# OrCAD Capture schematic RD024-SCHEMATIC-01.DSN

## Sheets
1 3: size A3
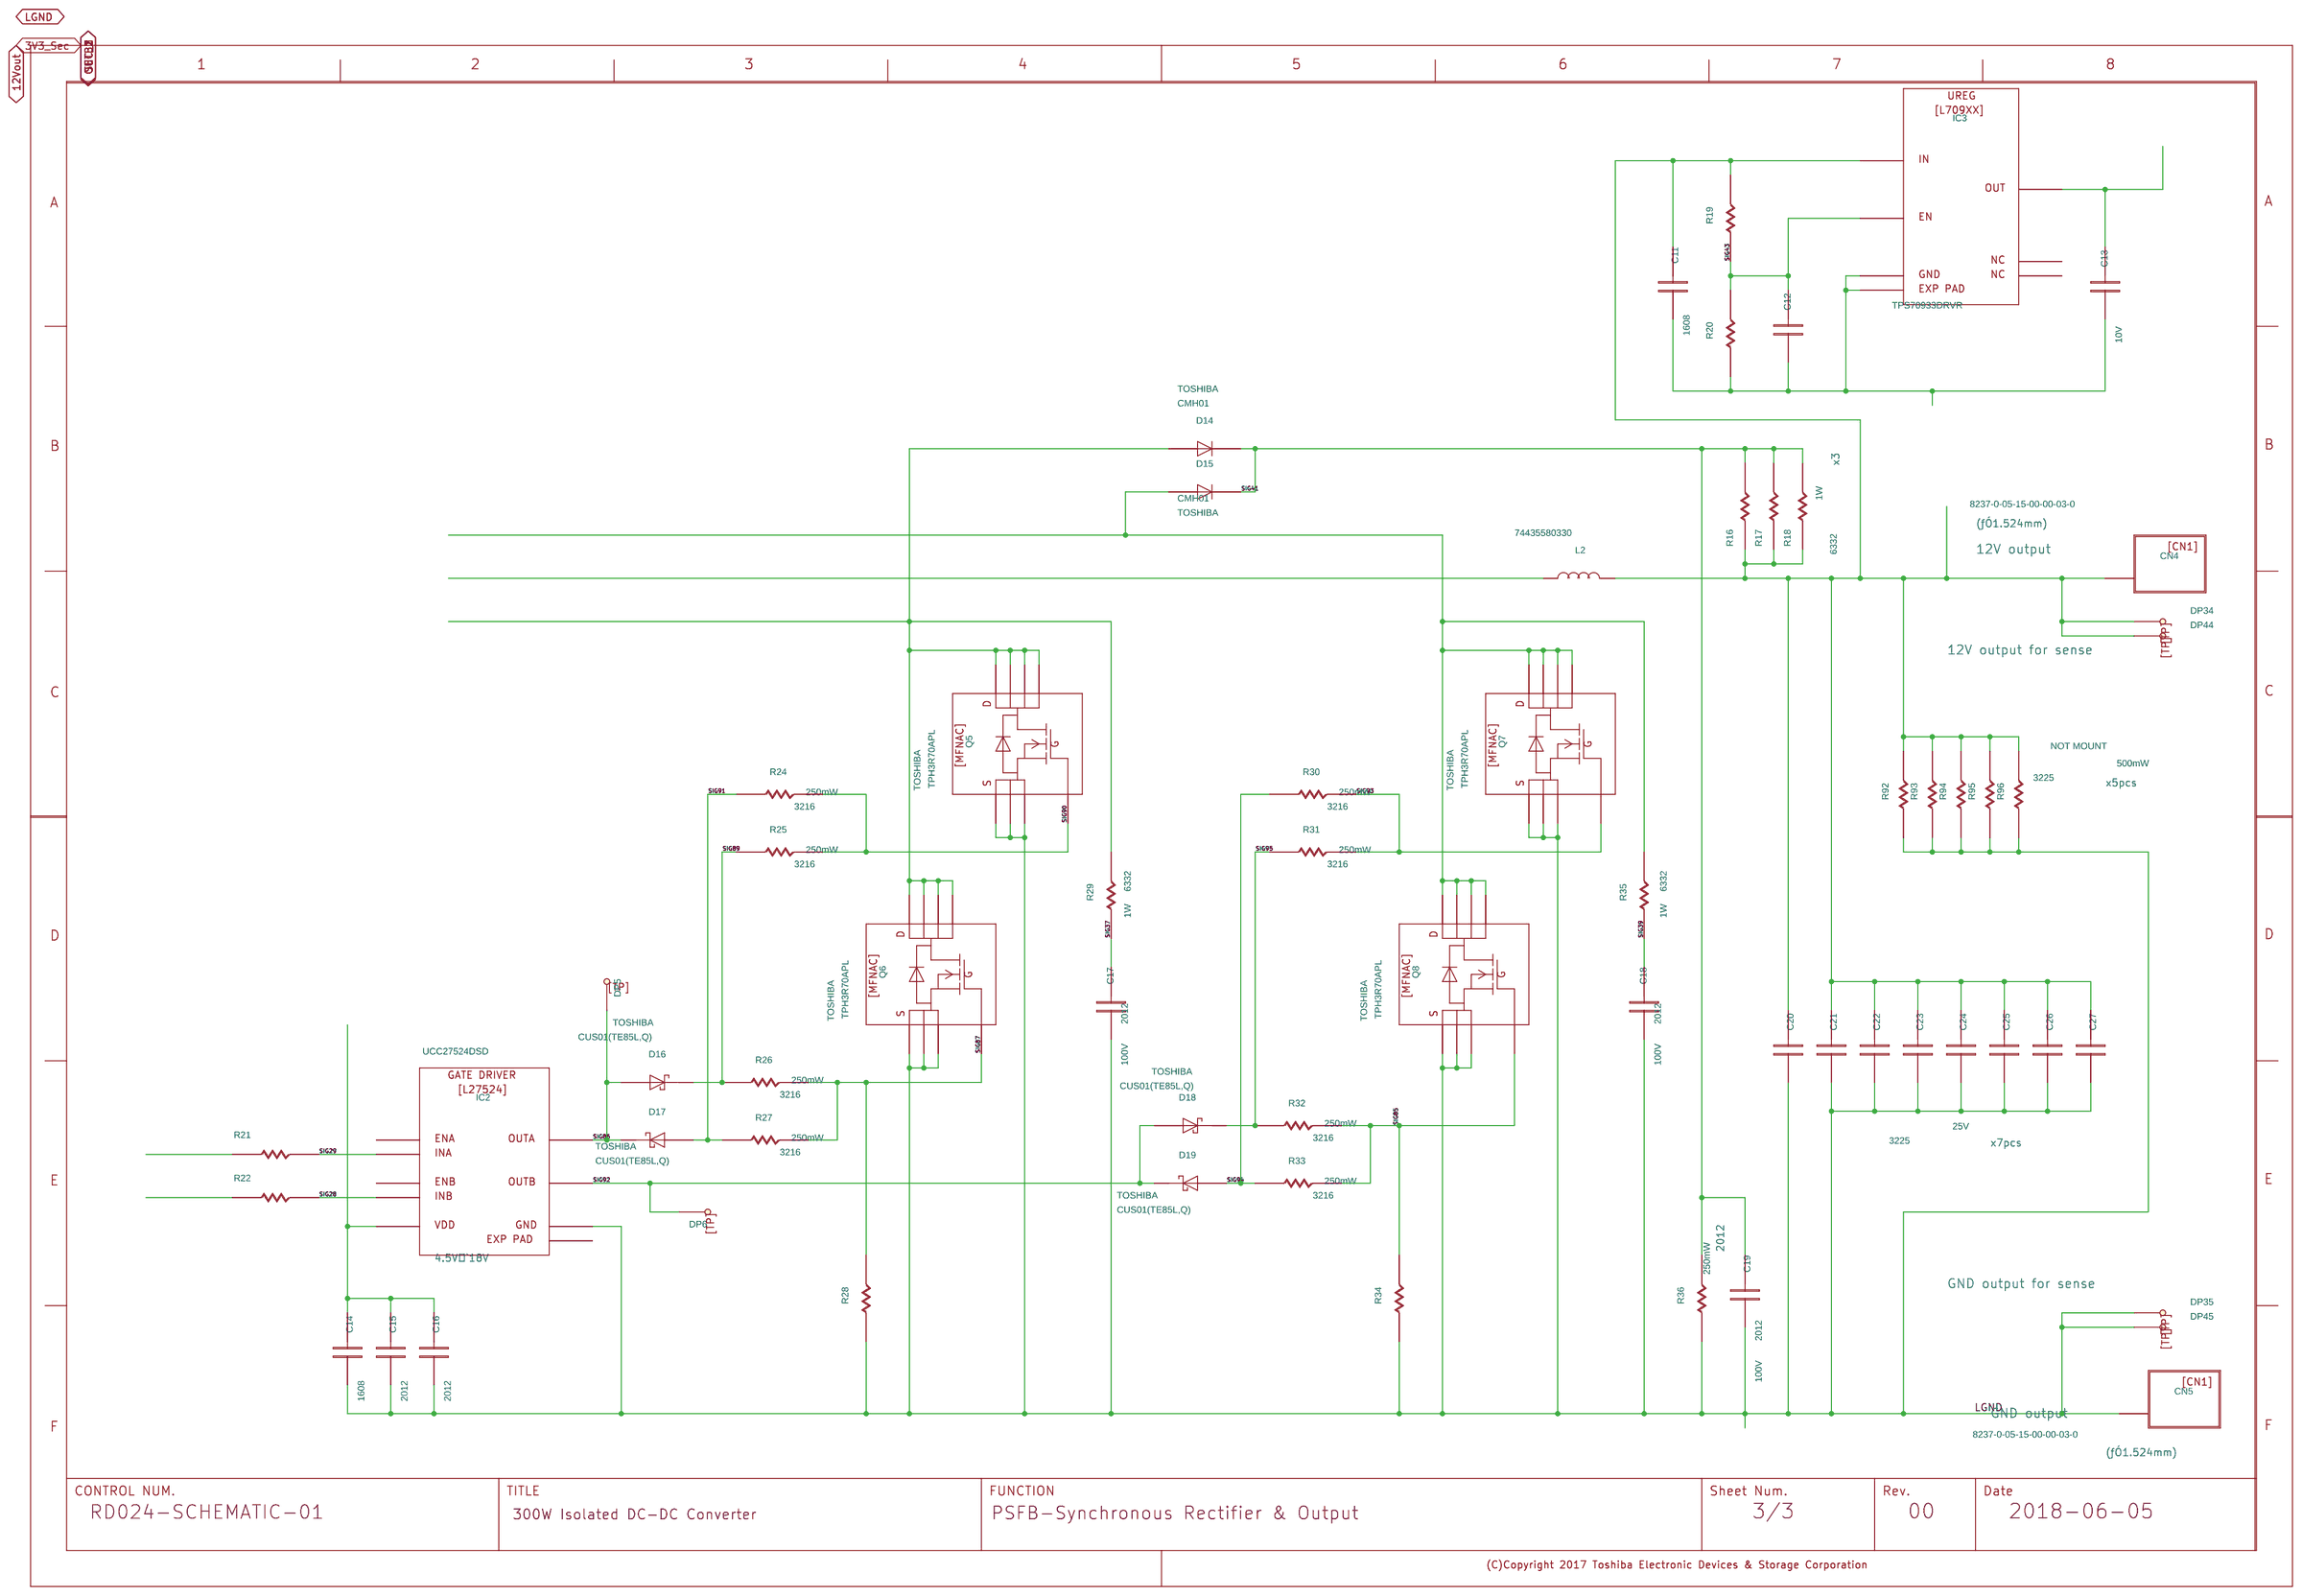
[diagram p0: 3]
2 2: size A3
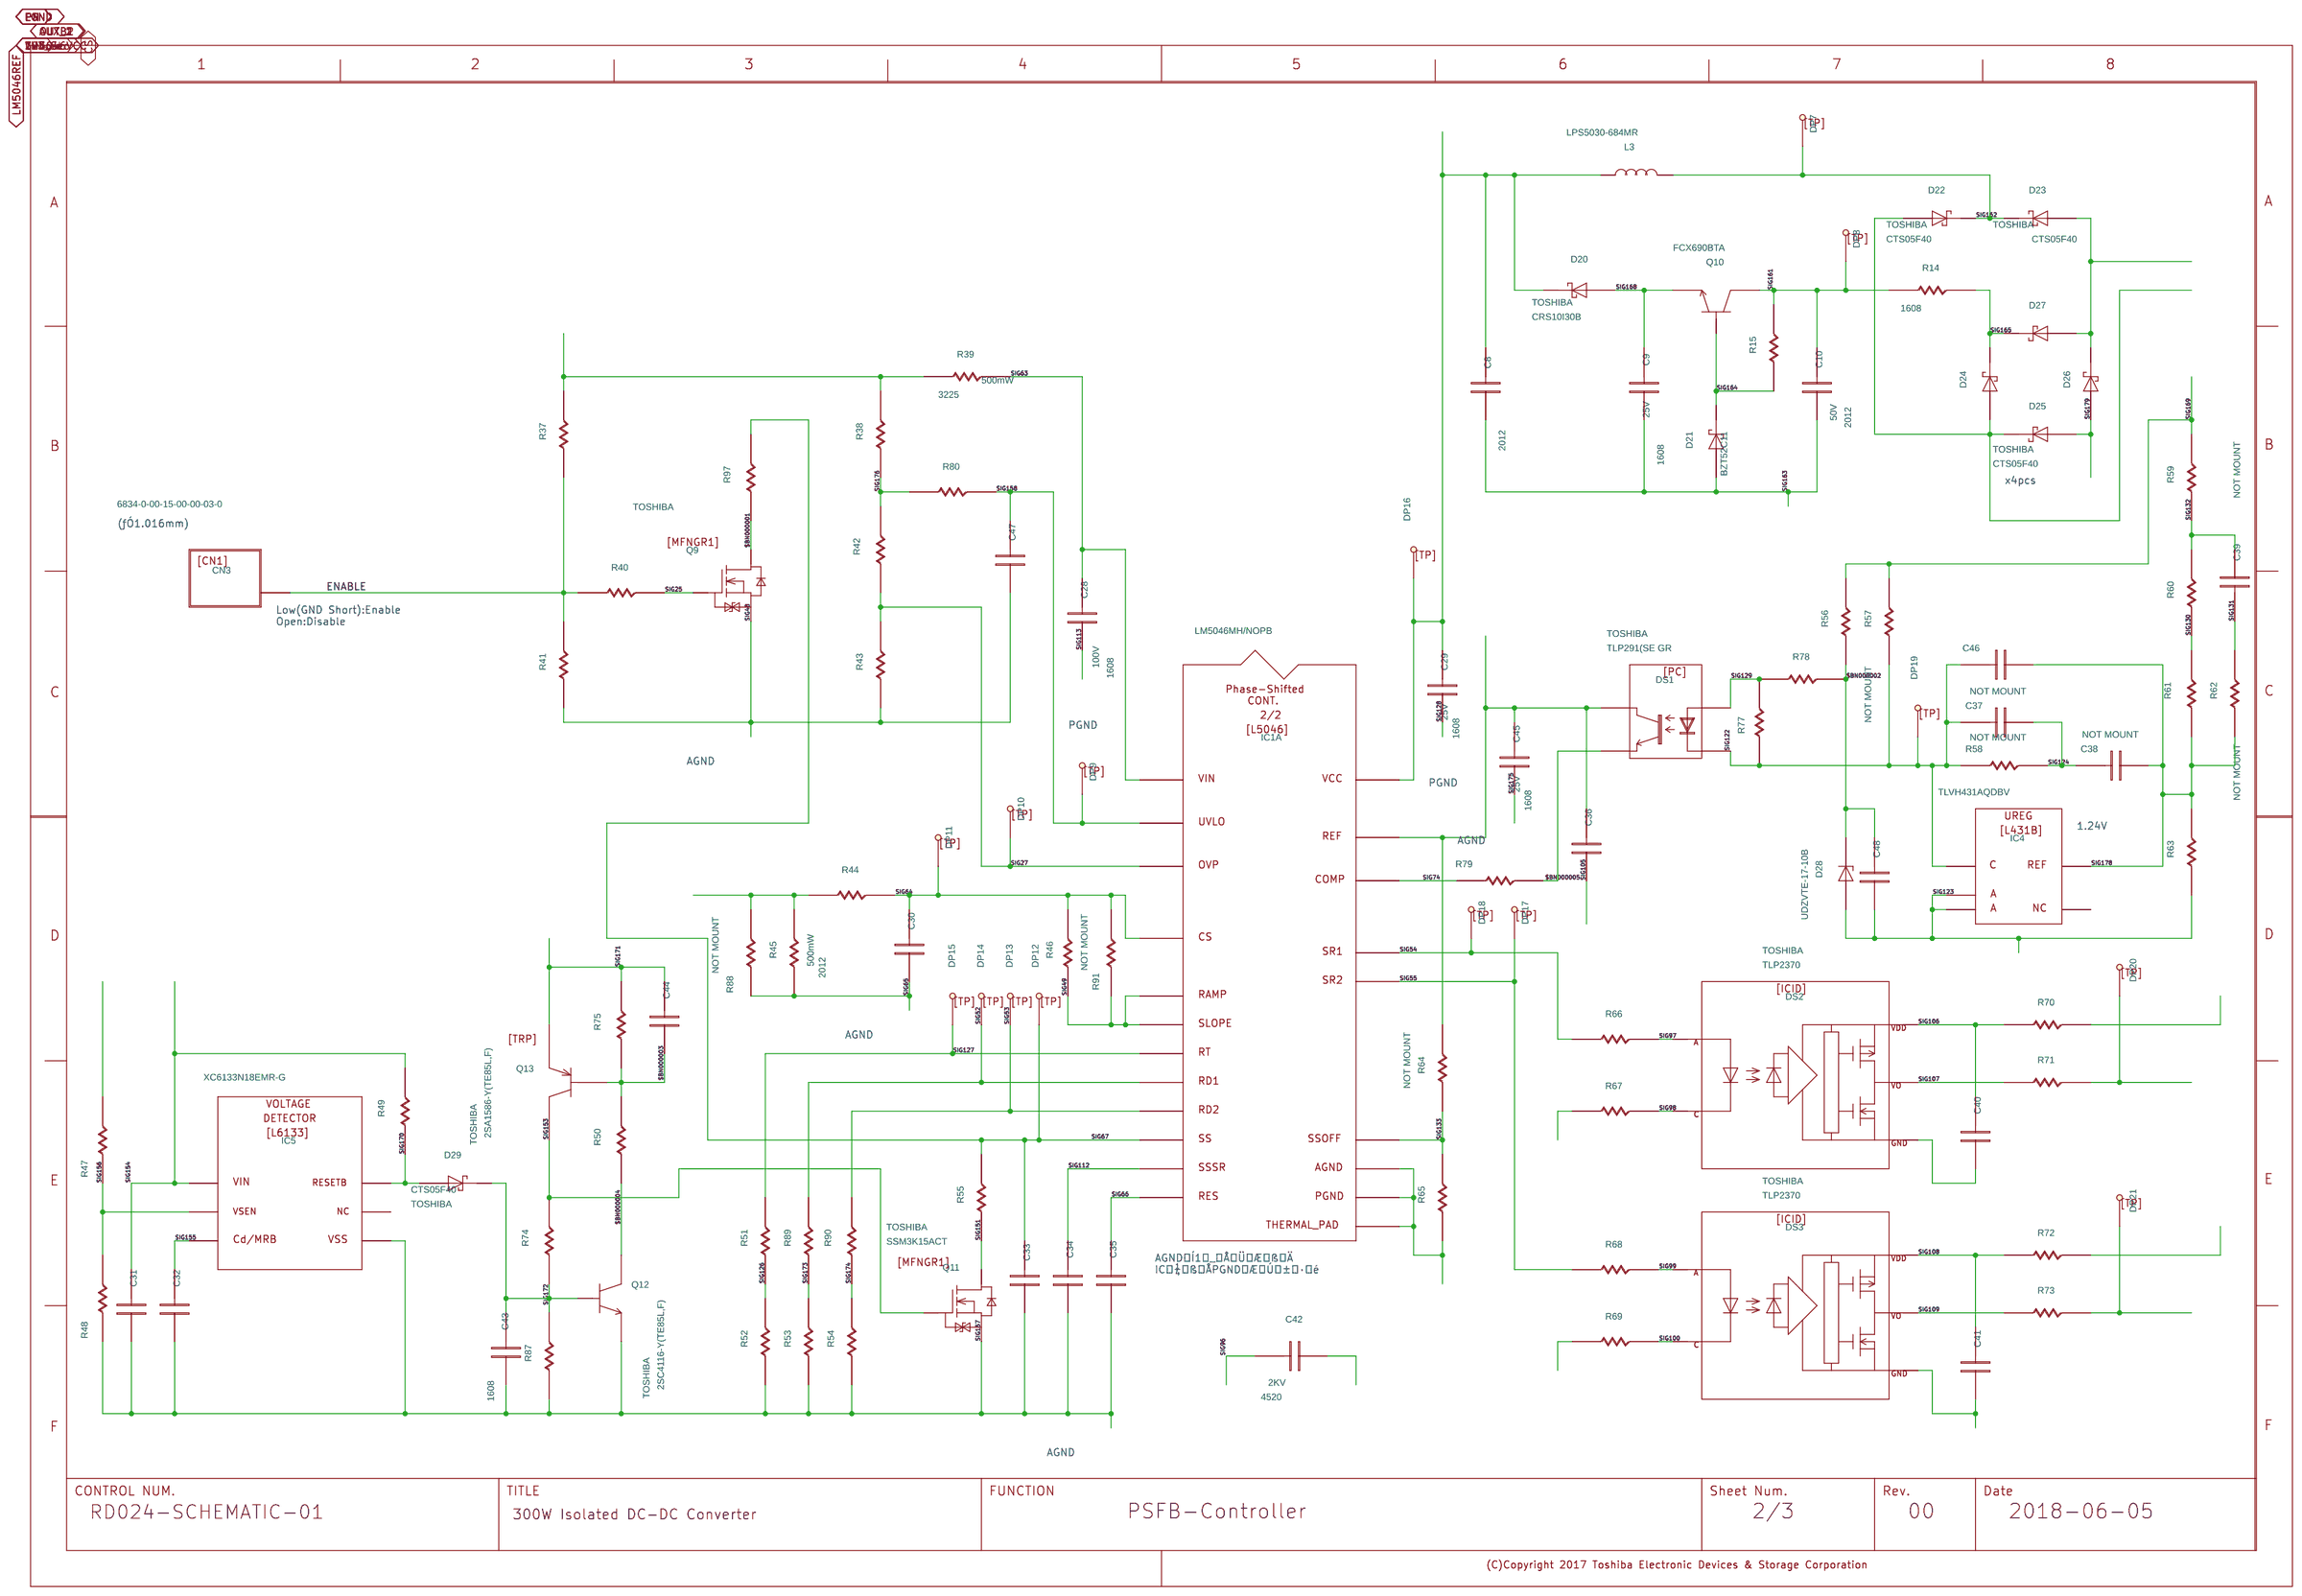
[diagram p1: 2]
3 1: size A3
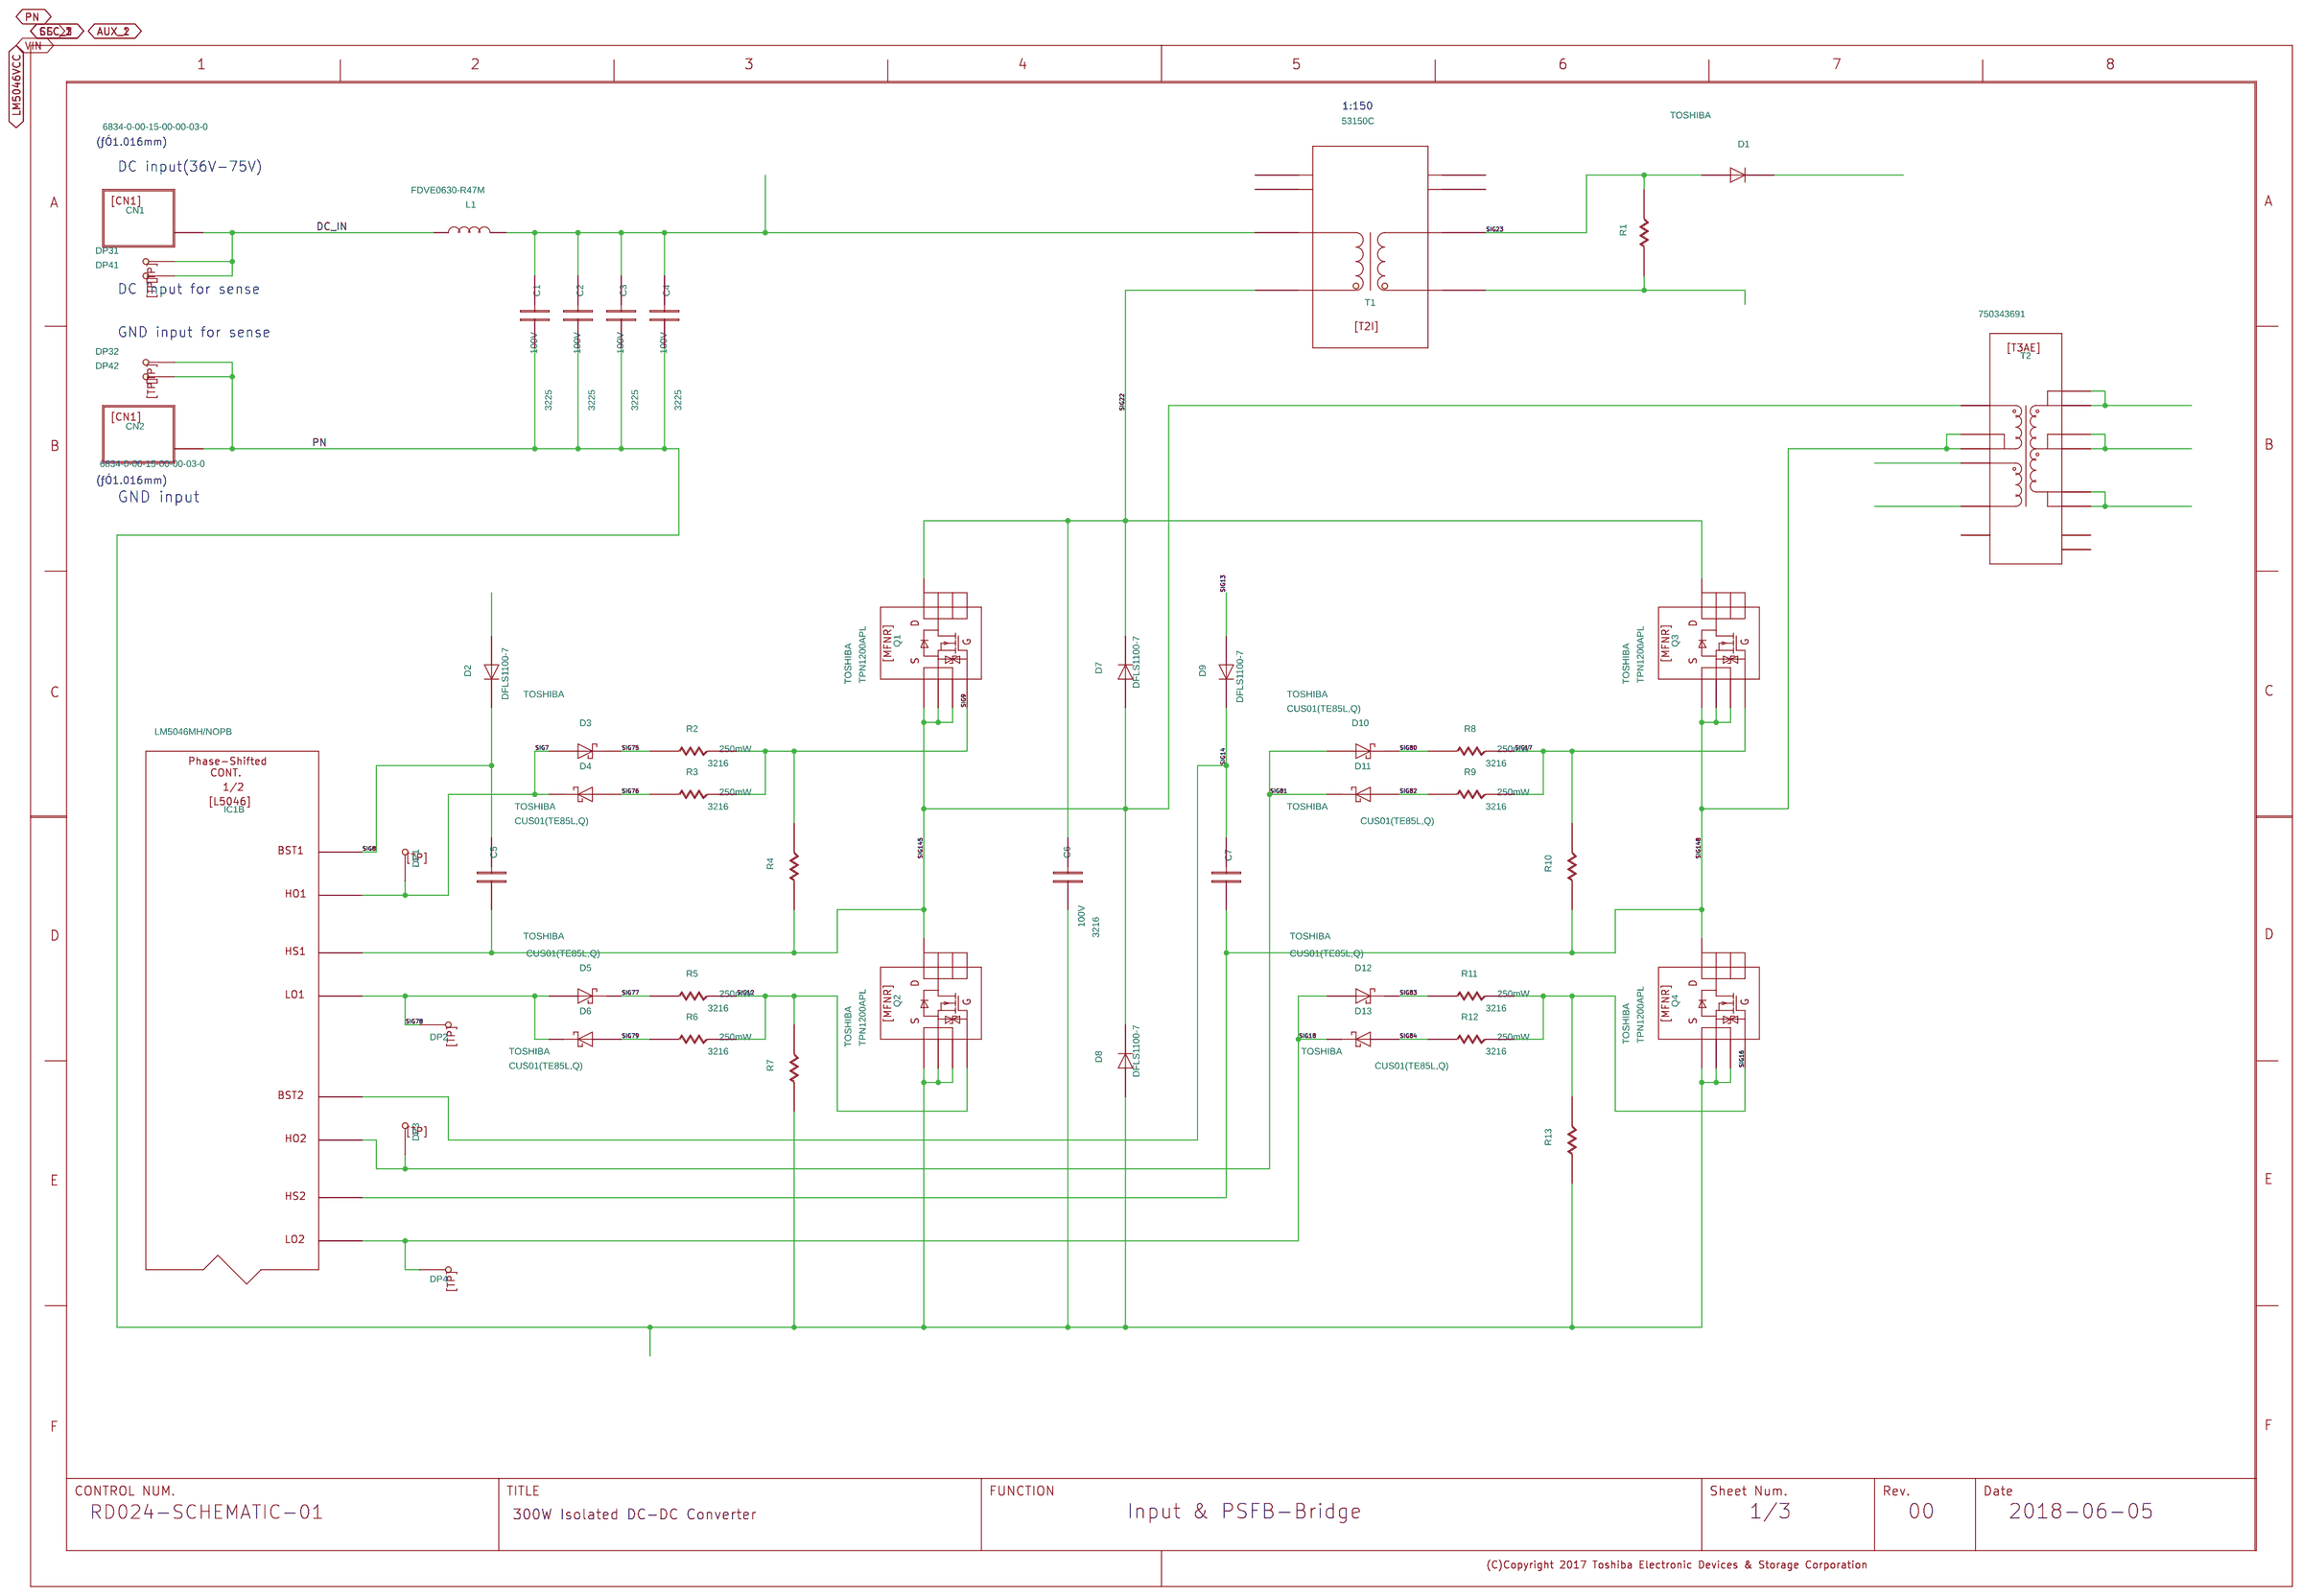
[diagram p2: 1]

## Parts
sheet 1
C1  10uF
C2  10uF
C3  10uF
C4  10uF
C5  100nF
C6  470nF
C7  100nF
CN1  CN1
CN2  CN1
D1  1SS352(TPH3,F)1-1E1A
D2  D
D3  CUS01(TE85L,Q)
D4  CUS01(TE85L,Q)
D5  CUS01(TE85L,Q)
D6  CUS01(TE85L,Q)
D7  D
D8  D
D9  D
D10  CUS01(TE85L,Q)
D11  CUS01(TE85L,Q)
D12  CUS01(TE85L,Q)
D13  CUS01(TE85L,Q)
DP1  TP
DP2  TP
DP3  TP
DP4  TP
DP31  TP
DP32  TP
DP41  TP
DP42  TP
L1  0.47uH
Q1  MFNR
Q2  MFNR
Q3  MFNR
Q4  MFNR
R1  10K(J)
R2  10(G)
R3  0
R4  10K(J)
R5  10(G)
R6  0
R7  10K(J)
R8  0
R9  0
R10  10K(J)
R11  0
R12  0
R13  10K(J)
T1  T2I
T2  T3AE
U?#2  WAKU_DEF100
sheet 2
C8  2.2uF
C9  1uF
C10  1uF
C28  100nF
C29  1uF
C30  100pF
C31  100nF
C32  100nF
C33  22nF
C34  100nF
C35  10nF
C36  100nF
C37  100pF
C38  15nF
C39  15nF
C40  100nF
C41  100nF
C42  1500pF
C43  1uF
C44  100nF
C45  1uF
C46  100nF
C47  1nF
C48  100nF
CN3  CN1
D20  SBD
D21  SBD
D22  SBD
D23  SBD
D24  SBD
D25  SBD
D26  SBD
D27  SBD
D28  ZD
D29  SBD
DP7  TP
DP8  TP
DP9  TP
DP10  TP
DP11  TP
DP12  TP
DP13  TP
DP14  TP
DP15  TP
DP16  TP
DP17  TP
DP18  TP
DP19  TP
DP20  TP
DP21  TP
DS1  PC
DS2  ICID
DS3  ICID
IC1  L5046_1  (sections A,B)
IC4  L431B
IC5  L6133
L3  680uH
Q9  SSM3K15ACT
Q10  TRN
Q11  SSM3K15ACT
Q12  2SC4116-Y(TE85L,F)
Q13  2SA1586-Y(TE85L,F)
R14  2.2(J)
R15  5.1K(J)
R37  1M(J)
R38  100K(J)
R39  20
R40  100K(J)
R41  220K(J)
R42  2.49K(D)
R43  1.6K(D)
R44  1K(J)
R45  8.2(F)
R46  3.3K(D)
R47  110K(D)
R48  16K(D)
R49  10K(J)
R50  10K(J)
R51  27K(D)
R52  0(X)
R53  20K(D)
R54  20K(D)
R55  1K(J)
R56  330(J)
R57  10K(J)
R58  620(F)
R59  49.9(F)
R60  1.2K(D)
R61  18K(D)
R62  182(F)
R63  2.2K(D)
R64  0(X)
R65  0(X)
R66  1K(F)
R67  910(F)
R68  1K(F)
R69  910(F)
R70  0(X)
R71  0(X)
R72  0(X)
R73  0(X)
R74  10K(J)
R75  10K(J)
R77  470(J)
R78  1.2K(F)
R79  2.2K(J)
R80  1(J)
R87  10K(J)
R88  9.1(J)
R89  7.5K(D)
R90  10K(J)
R91  0(X)
R97  1K(J)
U?#1  WAKU_DEF100
sheet 3
C11  1uF
C12  100nF
C13  2.2uF
C14  1uF
C15  10uF
C16  10uF
C17  470pF
C18  470pF
C19  220nF
C20  100nF
C21  22uF
C22  22uF
C23  22uF
C24  22uF
C25  22uF
C26  22uF
C27  22uF
CN4  CN1
CN5  CN1
D14  D
D15  D
D16  CUS01(TE85L,Q)
D17  CUS01(TE85L,Q)
D18  CUS01(TE85L,Q)
D19  CUS01(TE85L,Q)
DP5  TP
DP6  TP
DP34  TP
DP35  TP
DP44  TP
DP45  TP
IC2  L27524
IC3  L709XXA
L2  3.3uH
Q5  MFNAC
Q6  MFNAC
Q7  MFNAC
Q8  MFNAC
R16  6.8K
R17  6.8K
R18  6.8K
R19  240K(F)
R20  24K(F)
R21  1K(J)
R22  1K(J)
R24  0
R25  0
R26  0
R27  0
R28  10K(J)
R29  15(J)
R30  0
R31  0
R32  0
R33  0
R34  10K(J)
R35  15(J)
R36  100K
R92  750(F)
R93  750(F)
R94  750(F)
R95  750(F)
R96  750(F)
U?#3  WAKU_DEF100

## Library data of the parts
C1-C4 = C: ADSCNVFLAG: ON; ADSCOMPONENTNAME: C_3225; ADSMODELNAME: s_GRM32EC80G107ME20L; CAPACITANCETOLE: M; CDMASTERCADCELG: DC903A; COMP: PRT_2; COMPONENTTYPE: 4; GCOUNT: 1; ICX_PART_MODEL: CON_100U; MAXGCOUNT: 1; NOMINALCAPACITA: 100u; OUMECLASSIFICATION: ƒZƒ‰ƒ~ƒbƒNƒRƒ“ƒfƒ“ƒT; OUMEMAKER: MRT ºc»ì; OUMEMAKERKATAMEI: GRM32EC80G107ME20L; QUADMODEL: CON_100U; RATEDVOLTAGE: 4; SIZECODESMD: 3225; SQ_PART_MODEL: CON_100U; VALUE2: 100V; VALUE3: GRM32EC72A106KE05#
C5 C7 C12 C20 C31 C32 C34 C36 C40 C41 C44 C46 C48 = C: ADSCNVFLAG: ON; ADSCOMPONENTNAME: C_1005; ADSMODELNAME: s_GRM155R71E104KE14D; CAPACITANCETOLE: K; CDMASTERCADCELG: KC0005; COMP: PRT_4; COMPONENTTYPE: 4; GCOUNT: 1; ICX_PART_MODEL: CON_100N; MAXGCOUNT: 1; NOMINALCAPACITA: 100n; OUMECLASSIFICATION: ƒZƒ‰ƒ~ƒbƒNƒRƒ“ƒfƒ“ƒT; OUMEMAKER: MRT ºc»ì; OUMEMAKERKATAMEI: GRM155R71E104KE14D; QUADMODEL: CON_100N; RATEDVOLTAGE: 25; SIZECODESMD: 1005; SQ_PART_MODEL: CON_100N; VALUE2: 25V; VALUE3: GRM155R71E104KE14#
C6 = C: COMP: PRT_13; COMPCOMMENT: 3216; COMPONENTTYPE: 4; VALUE2: 100V; VALUE3: GRM31MR72A474KA35#
CN1-CN3 = CN1: COMP: PRT_16; COMPONENTTYPE: 4; VALUE3: 6834-0-00-15-00-00-03-0
D1 = D: COMP: PRT_3; COMPONENTTYPE: 4; GCOUNT: 1; MAXGCOUNT: 1; USERCOMPTEXT3: TOSHIBA
D2 D7-D9 = D: COMP: PRT_9; COMPONENTTYPE: 4; VALUE3: DFLS1100-7
D3-D6 D10-D13 D16-D19 = SBD: COMP: PRT_7; COMPONENTTYPE: 4; GCOUNT: 1; MAXGCOUNT: 1; OUMEPARTTYPE: D; USERCOMPTEXT3: TOSHIBA
DP1-DP21 DP31 DP32 DP34 DP35 DP41 DP42 DP44 DP45 = TP: COMP: PRT_10; COMPONENTTYPE: 4; GCOUNT: 1; MAXGCOUNT: 1
L1 = L: ADSCNVFLAG: ON; ADSCOMPONENTNAME: L_SMD; ADSMODELNAME: s_FDV0630_4R7M_P3; CDMASTERCADCELG: KD0074; COMP: PRT_1; COMPONENTTYPE: 4; GCOUNT: 1; INDUCTANCEMAX: 0; INDUCTANCEMIN: 0; MAXGCOUNT: 1; MOUNTINGFORMSMD: SMD; NOMINALINDUCTA1: 4.7u; NOMINALINDUCTA2: M; OUMECLASSIFICATION: •\–ÊŽÀ‘•—pŒÅ’èƒRƒCƒ‹; OUMEMAKER: TKO “ŒŒõ; OUMEMAKERKATAMEI: FDV0630-4R7M=P3; RATEDCURRENT: 3.3; VALUE3: FDVE0630-R47M
Q1-Q4 = MFNR: COMP: PRT_15; COMPONENTTYPE: 4; USERCOMPTEXT3: TOSHIBA; VALUE3: TPN1200APL
R1 R4 R7 R10 R13 R28 R34 R49 R50 R74 R75 R87 R90 = R: COMP: PRT_8; COMPONENTTYPE: 4; GCOUNT: 1; MAXGCOUNT: 1; SIZECODESMD: 1005; VALUE2: 63mW; VALUE3: ERJ2GEJ103X
R2 R5 = R: COMP: PRT_14; COMPONENTTYPE: 4; GCOUNT: 1; MAXGCOUNT: 1; SIZECODESMD: 3216; VALUE2: 250mW; VALUE3: RK73B2BTTD100G
R3 R6 R8 R9 R11 R12 R24-R27 R30-R33 = R: COMP: PRT_12; COMPCOMMENT: 3216; COMPONENTTYPE: 4; VALUE2: 250mW; VALUE3: RK73Z2BRTTD
T1 = T2I: COMP: PRT_11; COMPONENTTYPE: 4; VALUE3: 53150C
T2 = T3AE: COMP: PRT_17; COMPONENTTYPE: 4; VALUE3: 750343691
U?#2 = WAKU_DEF100: COMPONENTTYPE: 2; DATE: 2018-06-05; DESIGNED: TOSHIBA; DRAWINGNUMBER: RD024-SCHEMATIC-01; FUNCTION: Input & PSFB-Bridge; PAGENUMBER: 01; REVISION: 00; SAVEAREA0: -45080,-4508,463680,304612; SHEETNUMBER: 1/3; TIME: 09:33:31; TITLE: 300W Isolated DC-DC Converter; UPDATEDATE: 2018/06/22; UPDATETIME: 14:09:13; UPDATEUSER: d5009410
C8 = C: ADSCNVFLAG: ON; ADSCOMPONENTNAME: C_2012; ADSMODELNAME: s_GRM21BR71E225KA73L@@; CAPACITANCETOLE: K; COMP: PRT_39; COMPONENTTYPE: 4; GCOUNT: 1; ICX_PART_MODEL: CON_2.2U; MAXGCOUNT: 1; NOMINALCAPACITA: 2.2u; OUMECLASSIFICATION: ƒZƒ‰ƒ~ƒbƒNƒRƒ“ƒfƒ“ƒT; OUMEMAKER: MRT ºc»ì; OUMEMAKERKATAMEI: GRM21BR71E225KA73L@@; QUADMODEL: CON_2.2U; RATEDVOLTAGE: 25; SIZECODESMD: 2012; SQ_PART_MODEL: CON_2.2U; VALUE2: 25V; VALUE3: GRM21BR71E225KE11#
C9 C11 C14 C29 C45 = C: ADSCNVFLAG: ON; ADSCOMPONENTNAME: C_1608; ADSMODELNAME: s_GRM188B31E105KA75D; CAPACITANCETOLE: K; CDMASTERCADCELG: KC0008; COMP: PRT_34; COMPONENTTYPE: 4; GCOUNT: 1; ICX_PART_MODEL: CON_1U; MAXGCOUNT: 1; NOMINALCAPACITA: 1u; OUMECLASSIFICATION: ƒZƒ‰ƒ~ƒbƒNƒRƒ“ƒfƒ“ƒT; OUMEMAKER: MRT ºc»ì; OUMEMAKERKATAMEI: GRM188B31E105KA75D; QUADMODEL: CON_1U; RATEDVOLTAGE: 25; SIZECODESMD: 1608; SQ_PART_MODEL: CON_1U; TEMPCHARACTERI2: B; VALUE2: 25V; VALUE3: GRJ188R71E105KE11#
C10 = C: ADSCNVFLAG: ON; ADSCOMPONENTNAME: C_2012; ADSMODELNAME: s_GCM21BR71H105KA01L@@; CAPACITANCETOLE: K; CDMASTERCADCELG: KC0136; COMP: PRT_33; COMPONENTTYPE: 4; GCOUNT: 1; ICX_PART_MODEL: CON_1U; MAXGCOUNT: 1; NOMINALCAPACITA: 1u; OUMECLASSIFICATION: ƒZƒ‰ƒ~ƒbƒNƒRƒ“ƒfƒ“ƒT; OUMEMAKER: MRT ºc»ì; OUMEMAKERKATAMEI: GCM21BR71H105KA01L@@; QUADMODEL: CON_1U; RATEDVOLTAGE: 50; SIZECODESMD: 2012; SQ_PART_MODEL: CON_1U; VALUE2: 50V; VALUE3: GRJ21BR71H105KE01#
C28 = C: ADSCNVFLAG: ON; ADSCOMPONENTNAME: C_1608; ADSMODELNAME: s_GRM188R72A104KA35D; CAPACITANCETOLE: K; CDMASTERCADCELG: KC0008; COMP: PRT_51; COMPONENTTYPE: 4; GCOUNT: 1; ICX_PART_MODEL: CON_100N; MAXGCOUNT: 1; NOMINALCAPACITA: 100n; OUMECLASSIFICATION: ƒZƒ‰ƒ~ƒbƒNƒRƒ“ƒfƒ“ƒT; OUMEMAKER: MRT ºc»ì; OUMEMAKERKATAMEI: GRM188R72A104KA35D; QUADMODEL: CON_100N; RATEDVOLTAGE: 100; SIZECODESMD: 1608; SQ_PART_MODEL: CON_100N; VALUE2: 100V; VALUE3: GRM188R72A104KA35#
C30 = C: ADSCNVFLAG: ON; ADSCOMPONENTNAME: C_1005; ADSMODELNAME: s_GRM1555C1H101JA01D; CAPACITANCETOLE: J; CDMASTERCADCELG: KC0005; COMP: PRT_55; COMPONENTTYPE: 4; GCOUNT: 1; ICX_PART_MODEL: CON_100P; MAXGCOUNT: 1; NOMINALCAPACITA: 100p; OUMECLASSIFICATION: ƒZƒ‰ƒ~ƒbƒNƒRƒ“ƒfƒ“ƒT; OUMEMAKER: MRT ºc»ì; OUMEMAKERKATAMEI: GRM1555C1H101JA01D; QUADMODEL: CON_100P; RATEDVOLTAGE: 50; SIZECODESMD: 1005; SQ_PART_MODEL: CON_100P; VALUE2: 50V; VALUE3: GRM1555C1H101JA01#
C33 = C: ADSCNVFLAG: ON; ADSCOMPONENTNAME: C_1005; ADSMODELNAME: s_GRM155R71E223KA61D; CAPACITANCETOLE: K; CDMASTERCADCELG: KC0005; COMP: PRT_20; COMPONENTTYPE: 4; GCOUNT: 1; ICX_PART_MODEL: CON_22N; MAXGCOUNT: 1; NOMINALCAPACITA: 22n; OUMECLASSIFICATION: ƒZƒ‰ƒ~ƒbƒNƒRƒ“ƒfƒ“ƒT; OUMEMAKER: MRT ºc»ì; OUMEMAKERKATAMEI: GRM155R71E223KA61D; QUADMODEL: CON_22N; RATEDVOLTAGE: 25; SIZECODESMD: 1005; SQ_PART_MODEL: CON_22N; VALUE2: 25V; VALUE3: GRM155R71E223KA61#
C35 = C: ADSCNVFLAG: ON; ADSCOMPONENTNAME: C_1005; ADSMODELNAME: s_GRM155R71E103KA01D; CAPACITANCETOLE: K; CDMASTERCADCELG: KC0005; COMP: PRT_19; COMPONENTTYPE: 4; GCOUNT: 1; ICX_PART_MODEL: CON_10N; MAXGCOUNT: 1; NOMINALCAPACITA: 10n; OUMECLASSIFICATION: ƒZƒ‰ƒ~ƒbƒNƒRƒ“ƒfƒ“ƒT; OUMEMAKER: MRT ºc»ì; OUMEMAKERKATAMEI: GRM155R71E103KA01D; QUADMODEL: CON_10N; RATEDVOLTAGE: 25; SIZECODESMD: 1005; SQ_PART_MODEL: CON_10N; VALUE2: 25V; VALUE3: GRM155R71E103KA01#
C37 = C: ADSCNVFLAG: ON; ADSCOMPONENTNAME: C_1005; ADSMODELNAME: s_GRM1555C1H101JA01D; CAPACITANCETOLE: J; CDMASTERCADCELG: KC0005; COMP: PRT_55; COMPONENTTYPE: 4; GCOUNT: 1; ICX_PART_MODEL: CON_100P; MAXGCOUNT: 1; NOMINALCAPACITA: 100p; NOTMOUNT: NOT MOUNT; OUMECLASSIFICATION: ƒZƒ‰ƒ~ƒbƒNƒRƒ“ƒfƒ“ƒT; OUMEMAKER: MRT ºc»ì; OUMEMAKERKATAMEI: GRM1555C1H101JA01D; QUADMODEL: CON_100P; RATEDVOLTAGE: 50; SIZECODESMD: 1005; SQ_PART_MODEL: CON_100P; VALUE2: 50V; VALUE3: GRM1555C1H101JA01#
C38 C39 = C: ADSCNVFLAG: ON; ADSCOMPONENTNAME: C_1005; ADSMODELNAME: s_C1005JB1H153KT; CAPACITANCETOLE: K; CDMASTERCADCELG: KC0005; COMP: PRT_23; COMPONENTTYPE: 4; GCOUNT: 1; ICX_PART_MODEL: CON_15N; MAXGCOUNT: 1; NOMINALCAPACITA: 15n; NOTMOUNT: NOT MOUNT; OUMECLASSIFICATION: ƒZƒ‰ƒ~ƒbƒNƒRƒ“ƒfƒ“ƒT; OUMEMAKER: TDK ‚s‚c‚j; OUMEMAKERKATAMEI: C1005JB1H153KT; QUADMODEL: CON_15N; RATEDVOLTAGE: 50; SIZECODESMD: 1005; SQ_PART_MODEL: CON_15N; TEMPCHARACTERI2: B; VALUE2: 25V; VALUE3: GRM155R71E153KA61#
C42 = C: ADSCNVFLAG: ON; ADSCOMPONENTNAME: C_4520; ADSMODELNAME: s_GR442QR73D102KW01L; CAPACITANCETOLE: K; CDMASTERCADCELG: KC0071; COMP: PRT_22; COMPONENTTYPE: 4; GCOUNT: 1; ICX_PART_MODEL: CON_1N; MAXGCOUNT: 1; NOMINALCAPACITA: 1n; OUMECLASSIFICATION: ƒZƒ‰ƒ~ƒbƒNƒRƒ“ƒfƒ“ƒT; OUMEMAKER: MRT ºc»ì; OUMEMAKERKATAMEI: GR442QR73D102KW01L; QUADMODEL: CON_1N; RATEDVOLTAGE: 2K; SIZECODESMD: 4520; SQ_PART_MODEL: CON_1N; VALUE2: 2KV; VALUE3: GR442QR73D152KW01-01
C43 = C: COMP: PRT_5; COMPCOMMENT: 1608; COMPONENTTYPE: 4; VALUE2: 25V; VALUE3: GRJ188R71E105KE11#
C47 = C: ADSCNVFLAG: ON; ADSCOMPONENTNAME: C_1005; ADSMODELNAME: s_GRM1552C1H102JA01D; CAPACITANCETOLE: J; CDMASTERCADCELG: KC0005; COMP: PRT_50; COMPONENTTYPE: 4; GCOUNT: 1; ICX_PART_MODEL: CON_1N; MAXGCOUNT: 1; NOMINALCAPACITA: 1n; OUMECLASSIFICATION: ƒZƒ‰ƒ~ƒbƒNƒRƒ“ƒfƒ“ƒT; OUMEMAKER: MRT ºc»ì; OUMEMAKERKATAMEI: GRM1552C1H102JA01D; QUADMODEL: CON_1N; RATEDVOLTAGE: 50; SIZECODESMD: 1005; SQ_PART_MODEL: CON_1N; TEMPCHARACTERI2: CH; VALUE2: 50V; VALUE3: GRM155R71H102KA01#
D20 = SBD: ADSMODELNAME: s_CRS10I30A; CDMASTERCADCELG: MMK0167; COMP: PRT_49; COMPONENTTYPE: 4; FORWARDVOLTAGEM: 0; GCOUNT: 1; MAXAVERAGEFORWA: 1; MAXGCOUNT: 1; MAXREPETITIVEPE: 30; MAXREVERSEVOLTA: 0; MOUNTINGFORMSMD: SMD; OUMECLASSIFICATION: ¬p®¬fq/VbgLoA_CI[h; OUMEMAKER: TSB “ŒŽÅ; OUMEMAKERKATAMEI: CRS10I30A; OUMEPARTTYPE: D; PEAKFORWARDVOLT: 390m; REVERSECURRENT: 60u; SAVEAREA0: -225,-91,12804,7836; UPDATEDATE: 2010/01/14; UPDATETIME: 14:20:16; UPDATEUSER: 19870035; USERCOMPTEXT3: TOSHIBA; VALUE3: CRS10I30B; ZENERVOLTAGEMAX: 0; ZENERVOLTAGEMIN: 0
D21 = SBD: COMP: PRT_35; COMPONENTTYPE: 4; VALUE3: BZT52C11
D22 D23 = SBD: ADSMODELNAME: s_CTS05S30; CDMASTERCADCELG: KCK0242; COMP: PRT_48; COMPONENTTYPE: 4; FORWARDVOLTAGEM: 0; GCOUNT: 1; MAXAVERAGEFORWA: 500m; MAXGCOUNT: 1; MAXREPETITIVEPE: 30; MAXREVERSEVOLTA: 0; MOUNTINGFORMSMD: SMD; OUMECLASSIFICATION: ¬p®¬fq/VbgLoA_CI[h; OUMEMAKER: TSB “ŒŽÅ; OUMEMAKERKATAMEI: CTS05S30; OUMEPARTTYPE: D; PEAKFORWARDVOLT: 0; REVERSECURRENT: 0; USERCOMPTEXT3: TOSHIBA; VALUE3: CTS05F40; ZENERVOLTAGEMAX: 0; ZENERVOLTAGEMIN: 0
D24-D27 D29 = SBD: COMP: PRT_48; COMPONENTTYPE: 4; USERCOMPTEXT3: TOSHIBA; VALUE3: CTS05F40
D28 = ZD: COMP: PRT_63; COMPONENTTYPE: 4; VALUE3: UDZVTE-17-10B
DS1 = PC: COMP: PRT_21; COMPONENTTYPE: 4; USERCOMPTEXT3: TOSHIBA; VALUE3: TLP291(SE GR
DS2 DS3 = ICID: COMP: PRT_72; COMPONENTTYPE: 4; USERCOMPTEXT3: TOSHIBA; VALUE3: TLP2370
IC1 = L5046_1: COMP: PRT_6; COMPONENTTYPE: 4; CaptureCellPackProp: L5046_1A; VALUE3: LM5046MH/NOPB
IC4 = L431B: COMP: PRT_56; COMPONENTTYPE: 4; VALUE3: TLVH431AQDBV
IC5 = L6133: COMP: PRT_58; COMPONENTTYPE: 4; VALUE3: XC6133N18EMR-G
L3 = L: ADSCNVFLAG: ON; ADSCOMPONENTNAME: L_SMD; ADSMODELNAME: s_XAL5030_472ME_HDD; CDMASTERCADCELG: KCK0316; COMP: PRT_37; COMPONENTTYPE: 4; GCOUNT: 1; INDUCTANCEMAX: 0; INDUCTANCEMIN: 0; MAXGCOUNT: 1; MOUNTINGFORMSMD: SMD; NOMINALINDUCTA1: 4.7u; NOMINALINDUCTA2: M; OUMECLASSIFICATION: •\–ÊŽÀ‘•—pŒÅ’èƒRƒCƒ‹; OUMEMAKER: CCT ƒRƒCƒ‹ƒNƒ‰ƒtƒg; OUMEMAKERKATAMEI: XAL5030-472ME-HDD; RATEDCURRENT: 4.3; VALUE3: LPS5030-684MR
Q9 Q11 = MFNGR1: COMP: PRT_18; COMPONENTTYPE: 4; GCOUNT: 1; MAXGCOUNT: 1; OUMEPARTTYPE: Q; USERCOMPTEXT3: TOSHIBA
Q10 = TRN: COMP: PRT_36; COMPONENTTYPE: 4; VALUE3: FCX690BTA
Q12 = TRN: COMP: PRT_62; COMPONENTTYPE: 4; GCOUNT: 1; MAXGCOUNT: 1; OUMEPARTTYPE: Q; USERCOMPTEXT3: TOSHIBA
Q13 = TRP: COMP: PRT_61; COMPONENTTYPE: 4; GCOUNT: 1; MAXGCOUNT: 1; OUMEPARTTYPE: Q; USERCOMPTEXT3: TOSHIBA
R14 = R: COMP: PRT_41; COMPONENTTYPE: 4; GCOUNT: 1; MAXGCOUNT: 1; SIZECODESMD: 1608; VALUE2: 100mW; VALUE3: ERJ3GEYJ2R2V@@
R15 = R: COMP: PRT_40; COMPONENTTYPE: 4; GCOUNT: 1; MAXGCOUNT: 1; SIZECODESMD: 1005; VALUE2: 63mW; VALUE3: ERJ2GEJ512X
R37 = R: COMP: PRT_29; COMPONENTTYPE: 4; GCOUNT: 1; MAXGCOUNT: 1; SIZECODESMD: 1005; VALUE2: 63mW; VALUE3: ERJ2GEJ105X
R38 R40 = R: COMP: PRT_27; COMPONENTTYPE: 4; GCOUNT: 1; MAXGCOUNT: 1; SIZECODESMD: 1005; VALUE2: 63mW; VALUE3: ERJ2GEJ104X
R39 = R: ADSCNVFLAG: ON; ADSCOMPONENTNAME: R_3225; ADSMODELNAME: s_ERJ14YJ200H; CDMASTERCADCELG: DR903A; COMP: PRT_31; COMPONENTTYPE: 4; GCOUNT: 1; ICX_PART_MODEL: RES_20; MAXGCOUNT: 1; MOUNTINGFORMSMD: SMD; OUMECLASSIFICATION: \ÊÀpÅèïRí; OUMEMAKER: NAE pi\jbNGNgjbNfoCX; OUMEMAKERKATAMEI: ERJ14YJ200H; POWERRATING: 250m; QUADMODEL: RES_20; RESISTANCETOLER: J; SIZECODESMD: 3225; SQ_PART_MODEL: RES_20; VALUE2: 500mW; VALUE3: ERJ14YJ200U
R41 = R: COMP: PRT_26; COMPONENTTYPE: 4; GCOUNT: 1; MAXGCOUNT: 1; SIZECODESMD: 1005; VALUE2: 63mW; VALUE3: ERJ2GEJ224X
R42 = R: COMP: PRT_59; COMPONENTTYPE: 4; GCOUNT: 1; MAXGCOUNT: 1; SIZECODESMD: 1005; VALUE2: 63mW; VALUE3: ERJ2RHD2491X
R43 = R: COMP: PRT_28; COMPONENTTYPE: 4; GCOUNT: 1; MAXGCOUNT: 1; SIZECODESMD: 1005; VALUE2: 63mW; VALUE3: ERJ2RHD162X
R21 R22 R44 R55 R97 = R: COMP: PRT_30; COMPONENTTYPE: 4; GCOUNT: 1; MAXGCOUNT: 1; SIZECODESMD: 1005; VALUE2: 63mW; VALUE3: ERJ2GEJ102X
R45 = R: COMP: PRT_57; COMPCOMMENT: 2012; COMPONENTTYPE: 4; VALUE2: 500mW; VALUE3: ERJ6DQF8R2V
R46 = R: COMP: PRT_66; COMPONENTTYPE: 4; GCOUNT: 1; MAXGCOUNT: 1; SIZECODESMD: 1005; VALUE2: 63mW; VALUE3: ERJ2RHD332X
R47 = R: COMP: PRT_53; COMPONENTTYPE: 4; GCOUNT: 1; MAXGCOUNT: 1; SIZECODESMD: 1005; VALUE2: 63mW; VALUE3: ERJ2RKD114X
R48 = R: COMP: PRT_54; COMPONENTTYPE: 4; GCOUNT: 1; MAXGCOUNT: 1; SIZECODESMD: 1005; VALUE2: 63mW; VALUE3: ERJ2RHD163X
R51 = R: COMP: PRT_65; COMPONENTTYPE: 4; GCOUNT: 1; MAXGCOUNT: 1; SIZECODESMD: 1005; VALUE2: 63mW; VALUE3: ERJ2RHD273X
R52 R65 R70-R73 = R: COMP: PRT_25; COMPONENTTYPE: 4; GCOUNT: 1; MAXGCOUNT: 1; SIZECODESMD: 1005; VALUE2: 63mW; VALUE3: ERJ2GE0R00X
R53 R54 = R: COMP: PRT_52; COMPONENTTYPE: 4; GCOUNT: 1; MAXGCOUNT: 1; SIZECODESMD: 1005; VALUE2: 63mW; VALUE3: ERJ2RHD203X
R56 = R: COMP: PRT_71; COMPONENTTYPE: 4; GCOUNT: 1; MAXGCOUNT: 1; SIZECODESMD: 1005; VALUE2: 63mW; VALUE3: ERJ2GEJ331X
R57 = R: COMP: PRT_8; COMPONENTTYPE: 4; GCOUNT: 1; MAXGCOUNT: 1; NOTMOUNT: NOT MOUNT; SIZECODESMD: 1005; VALUE2: 63mW; VALUE3: ERJ2GEJ103X
R58 = R: COMP: PRT_70; COMPONENTTYPE: 4; GCOUNT: 1; MAXGCOUNT: 1; NOTMOUNT: NOT MOUNT; SIZECODESMD: 1005; VALUE2: 63mW; VALUE3: ERJ2RKF6200X
R59 = R: COMP: PRT_24; COMPONENTTYPE: 4; GCOUNT: 1; MAXGCOUNT: 1; SIZECODESMD: 1005; VALUE2: 63mW; VALUE3: ERJ2RKF49R9X
R60 = R: AUTHOR: Administrator; COMP: PRT_42; COMPONENTTYPE: 4; DATE: 2001/11/02; GCOUNT: 1; MAXGCOUNT: 1; MONOCODE: E00000333; SAVEAREA0: -17703,-20267,33725,19386; SIZECODESMD: 1005; TIME: 13:31:56; UPDATEDATE: 2002/10/10; UPDATETIME: 18:40:58; UPDATEUSER: user1; VALUE2: 63mW; VALUE3: ERJ2RHD122X
R61 = R: COMP: PRT_43; COMPONENTTYPE: 4; GCOUNT: 1; MAXGCOUNT: 1; SIZECODESMD: 1005; VALUE2: 63mW; VALUE3: ERJ2RHD183X
R62 = R: COMP: PRT_60; COMPONENTTYPE: 4; GCOUNT: 1; MAXGCOUNT: 1; NOTMOUNT: NOT MOUNT; SIZECODESMD: 1005; VALUE2: 63mW; VALUE3: RC0402FR-07182RL
R63 = R: COMP: PRT_44; COMPONENTTYPE: 4; GCOUNT: 1; MAXGCOUNT: 1; SIZECODESMD: 1005; VALUE2: 63mW; VALUE3: ERJ2RHD222X
R64 R91 = R: COMP: PRT_25; COMPONENTTYPE: 4; GCOUNT: 1; MAXGCOUNT: 1; NOTMOUNT: NOT MOUNT; SIZECODESMD: 1005; VALUE2: 63mW; VALUE3: ERJ2GE0R00X
R66 R68 = R: COMP: PRT_45; COMPONENTTYPE: 4; GCOUNT: 1; MAXGCOUNT: 1; SIZECODESMD: 1005; VALUE2: 63mW; VALUE3: ERJ2RKF1001X
R67 R69 = R: COMP: PRT_46; COMPONENTTYPE: 4; GCOUNT: 1; MAXGCOUNT: 1; SIZECODESMD: 1005; VALUE2: 63mW; VALUE3: RK73H1ETTP9100F
R77 = R: COMP: PRT_68; COMPONENTTYPE: 4; GCOUNT: 1; MAXGCOUNT: 1; SIZECODESMD: 1005; VALUE2: 63mW; VALUE3: ERJ2GEJ471X
R78 = R: COMP: PRT_69; COMPONENTTYPE: 4; GCOUNT: 1; MAXGCOUNT: 1; SIZECODESMD: 1005; VALUE2: 63mW; VALUE3: ERJ2RKF1201X
R79 = R: COMP: PRT_67; COMPONENTTYPE: 4; GCOUNT: 1; MAXGCOUNT: 1; SIZECODESMD: 1005; VALUE2: 63mW; VALUE3: ERJ2GEJ222X
R80 = R: COMP: PRT_32; COMPONENTTYPE: 4; GCOUNT: 1; MAXGCOUNT: 1; SIZECODESMD: 1005; VALUE2: 63mW; VALUE3: ERJ2GEJ1R0X
R88 = R: COMP: PRT_47; COMPONENTTYPE: 4; GCOUNT: 1; MAXGCOUNT: 1; NOTMOUNT: NOT MOUNT; SIZECODESMD: 1005; VALUE2: 63mW; VALUE3: ERJ2GEJ9R1X
R89 = R: COMP: PRT_64; COMPONENTTYPE: 4; GCOUNT: 1; MAXGCOUNT: 1; SIZECODESMD: 1005; VALUE2: 63mW; VALUE3: ERJ2RHD752X
U?#1 = WAKU_DEF100: COMPONENTTYPE: 2; DATE: 2018-06-05; DESIGNED: TOSHIBA; DRAWINGNUMBER: RD024-SCHEMATIC-01; FUNCTION: PSFB-Controller; PAGENUMBER: 03; REVISION: 00; SAVEAREA0: -45080,-4508,463680,304612; SHEETNUMBER: 2/3; TIME: 11:06:15; TITLE: 300W Isolated DC-DC Converter; UPDATEDATE: 2018/06/22; UPDATETIME: 14:09:25; UPDATEUSER: d5009410
C13 = C: ADSCNVFLAG: ON; ADSCOMPONENTNAME: C_1005; ADSMODELNAME: s_GRM155C71A225KE11D; CAPACITANCETOLE: K; CDMASTERCADCELG: KC0005; COMP: PRT_76; COMPONENTTYPE: 4; GCOUNT: 1; ICX_PART_MODEL: CON_2.2U; MAXGCOUNT: 1; NOMINALCAPACITA: 2.2u; OUMECLASSIFICATION: ƒZƒ‰ƒ~ƒbƒNƒRƒ“ƒfƒ“ƒT; OUMEMAKER: MRT ºc»ì; OUMEMAKERKATAMEI: GRM155C71A225KE11D; QUADMODEL: CON_2.2U; RATEDVOLTAGE: 10; SIZECODESMD: 1005; SQ_PART_MODEL: CON_2.2U; VALUE2: 10V; VALUE3: C1005X7S1A225K050BC
C15 C16 = C: ADSCNVFLAG: ON; ADSCOMPONENTNAME: C_2012; ADSMODELNAME: s_GRM21BC70G106ME45L; CAPACITANCETOLE: M; CDMASTERCADCELG: KC0006; COMP: PRT_75; COMPONENTTYPE: 4; GCOUNT: 1; ICX_PART_MODEL: CON_10U; MAXGCOUNT: 1; NOMINALCAPACITA: 10u; OUMECLASSIFICATION: ƒZƒ‰ƒ~ƒbƒNƒRƒ“ƒfƒ“ƒT; OUMEMAKER: MRT ºc»ì; OUMEMAKERKATAMEI: GRM21BC70G106ME45L; QUADMODEL: CON_10U; RATEDVOLTAGE: 4; SIZECODESMD: 2012; SQ_PART_MODEL: CON_10U; VALUE2: 25V; VALUE3: GRM21BC71E106KE11#
C17 C18 = C: COMP: PRT_85; COMPCOMMENT: 2012; COMPONENTTYPE: 4; VALUE2: 100V; VALUE3: GRM219R72A471KA01#
C19 = C: ADSCNVFLAG: ON; ADSCOMPONENTNAME: C_2012; ADSMODELNAME: s_GRM21AR72A224KAC5L; CAPACITANCETOLE: K; COMP: PRT_77; COMPONENTTYPE: 4; GCOUNT: 1; ICX_PART_MODEL: CON_220N; MAXGCOUNT: 1; NOMINALCAPACITA: 220n; OUMECLASSIFICATION: ƒZƒ‰ƒ~ƒbƒNƒRƒ“ƒfƒ“ƒT; OUMEMAKER: MRT ºc»ì; OUMEMAKERKATAMEI: GRM21AR72A224KAC5L; QUADMODEL: CON_220N; RATEDVOLTAGE: 100; SIZECODESMD: 2012; SQ_PART_MODEL: CON_220N; VALUE2: 100V; VALUE3: GRM21AR72A224KAC5#
C21-C27 = C: ADSCNVFLAG: ON; ADSCOMPONENTNAME: C_3225; ADSMODELNAME: s_GRM32ER71E226ME15L; CAPACITANCETOLE: M; CDMASTERCADCELG: KC0180; COMP: PRT_74; COMPONENTTYPE: 4; GCOUNT: 1; ICX_PART_MODEL: CON_22U; MAXGCOUNT: 1; NOMINALCAPACITA: 22u; OUMECLASSIFICATION: ƒZƒ‰ƒ~ƒbƒNƒRƒ“ƒfƒ“ƒT; OUMEMAKER: MRT ºc»ì; OUMEMAKERKATAMEI: GRM32ER71E226ME15L; QUADMODEL: CON_22U; RATEDVOLTAGE: 25; SIZECODESMD: 3225; SQ_PART_MODEL: CON_22U; VALUE2: 25V; VALUE3: GRM32ER71E226ME15#
CN4 CN5 = CN1: COMP: PRT_86; COMPONENTTYPE: 4; VALUE3: 8237-0-05-15-00-00-03-0
D14 D15 = D: COMP: PRT_38; COMPONENTTYPE: 4; USERCOMPTEXT3: TOSHIBA; VALUE3: CMH01
IC2 = L27524: COMP: PRT_87; COMPONENTTYPE: 4; VALUE3: UCC27524DSD
IC3 = L709XXA: COMP: PRT_78; COMPONENTTYPE: 4; VALUE3: TPS70933DRVR
L2 = L: COMP: PRT_73; COMPONENTTYPE: 4; VALUE3: 74435580330
Q5-Q8 = MFNAC: COMP: PRT_88; COMPONENTTYPE: 4; USERCOMPTEXT3: TOSHIBA; VALUE3: TPH3R70APL
R16-R18 = R: COMP: PRT_84; COMPCOMMENT: 6332; COMPONENTTYPE: 4; VALUE2: 1W; VALUE3: RK73BW3ATTE682J
R19 = R: COMP: PRT_81; COMPONENTTYPE: 4; GCOUNT: 1; MAXGCOUNT: 1; SIZECODESMD: 1005; VALUE2: 63mW; VALUE3: ERJ2RKF2403X
R20 = R: COMP: PRT_82; COMPONENTTYPE: 4; GCOUNT: 1; MAXGCOUNT: 1; SIZECODESMD: 1005; VALUE2: 63mW; VALUE3: ERJ2RKF2402X
R29 R35 = R: COMP: PRT_83; COMPONENTTYPE: 4; GCOUNT: 1; MAXGCOUNT: 1; SIZECODESMD: 6332; VALUE2: 1W; VALUE3: RK73B3ATTE150J
R36 = R: COMP: PRT_80; COMPONENTTYPE: 4; VALUE2: 250mW; VALUE3: RK73B2ATTD104J
R92-R96 = R: COMP: PRT_79; COMPONENTTYPE: 4; GCOUNT: 1; MAXGCOUNT: 1; NOTMOUNT: NOT MOUNT; SIZECODESMD: 3225; VALUE2: 500mW; VALUE3: RK73H2ETTE7500F
U?#3 = WAKU_DEF100: COMPONENTTYPE: 2; DATE: 2018-06-05; DESIGNED: TOSHIBA; DRAWINGNUMBER: RD024-SCHEMATIC-01; FUNCTION: PSFB-Synchronous Rectifier & Output; PAGENUMBER: 02; REVISION: 00; SAVEAREA0: -45080,-4508,463680,304612; SHEETNUMBER: 3/3; TIME: 17:17:20; TITLE: 300W Isolated DC-DC Converter; UPDATEDATE: 2018/06/22; UPDATETIME: 14:09:40; UPDATEUSER: d5009410

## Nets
3V3_Sec: C13.2 IC3.1 R70.2 R72.2
12Vout: C11.2 C14.2 C15.2 C16.2 C20.2 C21.2 C22.2 C23.2 C24.2 C25.2 C26.2 C27.2 CN4.1 DP34.1 DP44.1 IC2.6 IC3.6 L2.2 R16.1 R17.1 R18.1 R19.2 R56.2 R57.2 R59.2 R92.2 R93.2 R94.2 R95.2 R96.2
VIN: C1.2 C2.2 C3.2 C4.2 L1.2 R37.2 R38.2 R39.1 T1.7
$BN000001: Q9.D R97.1
$BN000002: C48.2 D28.C R56.1 R78.2
$BN000003: C44.1 Q13.B R50.2 R75.1
$BN000004: Q12.C R50.1
$BN000005: DS1.E R79.2
AUX_1: D23.A D26.C D27.A T2.2
AUX_2: D22.A D24.A D25.C T2.3
CS: D1.C R44.1 R45.2 R88.2
DC_IN: CN1.1 DP31.1 DP41.1 L1.1
ENABLE: CN3.1 R37.1 R40.1 R41.2
LGND: C11.1 C12.1 C13.1 C14.1 C15.1 C16.1 C17.1 C18.1 C19.1 C20.1 C21.1 C22.1 C23.1 C24.1 C25.1 C26.1 C27.1 C40.1 C41.1 C42.1 C48.1 CN5.1 D28.A DP35.1 DP45.1 DS2.4 DS3.4 IC2.3 IC3.3 IC3.7 IC4.2 IC4.5 Q5.1 Q5.2 Q5.3 Q6.1 Q6.2 Q6.3 Q7.1 Q7.2 Q7.3 Q8.1 Q8.2 Q8.3 R20.1 R28.1 R34.1 R36.1 R63.1 R92.1 R93.1 R94.1 R95.1 R96.1
LM5046REF: C31.2 C36.2 C44.2 C45.2 DS1.C IC1.7 IC5.1 Q13.E R49.2 R64.2 R75.2
LM5046VCC: C8.2 C29.2 D2.A D9.A D20.C DP16.1 IC1.21 L3.1 R47.2
OUTB1: DP20.1 R21.1 R71.2
OUTB2: DP21.1 R22.1 R73.2
PN: C1.1 C2.1 C3.1 C4.1 C6.1 C8.1 C9.1 C10.1 C28.1 C29.1 C30.1 C31.1 C32.1 C33.1 C34.1 C35.1 C36.1 C42.2 C43.1 C45.1 C47.1 CN2.1 D8.A D21.A D25.A D26.A DP32.1 DP42.1 IC1.9 IC1.22 IC1.29 IC5.5 Q2.1 Q2.2 Q2.3 Q4.1 Q4.2 Q4.3 Q9.S Q11.S Q12.E R1.1 R7.1 R13.1 R41.1 R43.1 R45.1 R48.1 R52.1 R53.1 R54.1 R65.1 R67.1 R69.1 R87.1 R88.1 T1.1
SEC_1: D15.A Q7.5 Q7.6 Q7.7 Q7.8 Q8.5 Q8.6 Q8.7 Q8.8 R35.2 T2.8 T2.9
SEC_2: L2.1 T2.6 T2.7
SEC_3: D14.A Q5.5 Q5.6 Q5.7 Q5.8 Q6.5 Q6.6 Q6.7 Q6.8 R29.2 T2.4 T2.5
SIG7: D3.A D4.C DP1.1 IC1.26
SIG8: C5.2 D2.C IC1.25
SIG9: Q1.4 R2.2 R3.2 R4.2
SIG12: Q2.4 R5.2 R6.2 R7.2
SIG14: C7.2 D9.C IC1.18
SIG16: Q4.4 R11.2 R12.2 R13.2
SIG17: Q3.4 R8.2 R9.2 R10.2
SIG18: D12.A D13.C DP4.1 IC1.20
SIG22: C6.2 D7.C Q1.5 Q3.5 T1.8
SIG23: D1.A R1.2 T1.3
SIG25: Q9.G R40.2
SIG27: DP10.1 IC1.2 R42.1 R43.2
SIG28: IC2.4 R22.2
SIG29: IC2.2 R21.2
SIG37: C17.2 R29.1
SIG39: C18.2 R35.1
SIG41: C19.2 D14.C D15.C R16.2 R17.2 R18.2 R36.2
SIG43: C12.2 IC3.4 R19.1 R20.2
SIG49: IC1.3 IC1.5 R46.1 R91.1
SIG52: DP14.1 IC1.10 R89.2
SIG53: DP13.1 IC1.11 R90.2
SIG54: DP18.1 IC1.24 R66.1
SIG55: DP17.1 IC1.19 R68.1
SIG63: C28.2 IC1.28 R39.2
SIG64: C30.2 DP11.1 IC1.4 R44.2 R46.2 R91.2
SIG66: C35.2 IC1.12
SIG67: C33.2 DP12.1 IC1.13 R55.2 R97.2
SIG74: IC1.6 R79.1
SIG75: D3.C R2.1
SIG76: D4.A R3.1
SIG77: D5.C R5.1
SIG78: D5.A D6.C DP2.1 IC1.23
SIG79: D6.A R6.1
SIG80: D10.C R8.1
SIG81: D10.A D11.C DP3.1 IC1.17
SIG82: D11.A R9.1
SIG83: D12.C R11.1
SIG84: D13.A R12.1
SIG85: Q8.4 R32.2 R33.2 R34.2
SIG86: D16.A D17.C DP5.1 IC2.7
SIG87: Q6.4 R26.2 R27.2 R28.2
SIG89: D16.C R25.1 R26.1
SIG90: Q5.4 R24.2 R25.2
SIG91: D17.A R24.1 R27.1
SIG92: D18.A D19.C DP6.1 IC2.5
SIG93: Q7.4 R30.2 R31.2
SIG94: D19.A R30.1 R33.1
SIG95: D18.C R31.1 R32.1
SIG97: DS2.1 R66.2
SIG98: DS2.3 R67.2
SIG99: DS3.1 R68.2
SIG100: DS3.3 R69.2
SIG106: C40.2 DS2.6 R70.1
SIG107: DS2.5 R71.1
SIG108: C41.2 DS3.6 R72.1
SIG109: DS3.5 R73.1
SIG112: C34.2 IC1.14
SIG122: C37.2 C46.2 DP19.1 DS1.CA IC4.3 R57.1 R58.1 R77.1
SIG124: C37.1 C38.2 R58.2
SIG126: R51.1 R52.2
SIG127: DP15.1 IC1.8 R51.2
SIG129: DS1.A R77.2 R78.1
SIG130: R60.1 R61.2
SIG131: C39.2 R62.2
SIG132: C39.1 R59.1 R60.2
SIG133: IC1.15 R64.1 R65.2
SIG145: C5.1 D7.A D8.C IC1.27 Q1.1 Q1.2 Q1.3 Q2.5 R4.1 T2.1
SIG148: C7.1 IC1.16 Q3.1 Q3.2 Q3.3 Q4.5 R10.1 T2.11 T2.12
SIG151: Q11.D R55.1
SIG153: Q11.G Q13.C R74.2
SIG155: C32.2 IC5.6
SIG156: IC5.4 R47.1 R48.2
SIG158: C47.2 DP9.1 IC1.1 R80.2
SIG161: C10.2 DP8.1 Q10.C R14.1 R15.2
SIG162: D22.C D23.C DP7.1 L3.2
SIG164: D21.C Q10.B R15.1
SIG165: D24.C D27.C R14.2
SIG168: C9.2 D20.A Q10.E
SIG170: D29.A IC5.2 R49.1
SIG172: C43.2 D29.C Q12.B R74.1 R87.2
SIG173: R53.2 R89.1
SIG174: R54.2 R90.1
SIG176: R38.1 R42.2 R80.1
SIG178: C38.1 C46.1 IC4.4 R61.1 R62.1 R63.2

Not connected (* = marked no-connect by the designer): IC2 1 8 9; IC3 2 5; IC4 1; IC5 3; T1 2 4 5 6; T2 10 13 14

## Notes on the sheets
sheet 1
- x3
- (ƒÓ1.524mm)
- 12V output
- 12V output for sense
- x5pcs
- x7pcs
- 4.5V`18V
- 2012
- GND output for sense
- GND output
- (ƒÓ1.524mm)
sheet 2
- x4pcs
- (ƒÓ1.016mm)
- Low(GND Short):Enable
  Open:Disable
- PGND
- AGND
- PGND
- 1.24V
- AGND
- AGND
- AGNDÍ1_ÅÜÆßÄ
  IC¼ßÅPGNDÆÚ±·é
- AGND
sheet 3
- 1:150
- (ƒÓ1.016mm)
- DC input(36V-75V)
- DC input for sense
- GND input for sense
- (ƒÓ1.016mm)
- GND input
